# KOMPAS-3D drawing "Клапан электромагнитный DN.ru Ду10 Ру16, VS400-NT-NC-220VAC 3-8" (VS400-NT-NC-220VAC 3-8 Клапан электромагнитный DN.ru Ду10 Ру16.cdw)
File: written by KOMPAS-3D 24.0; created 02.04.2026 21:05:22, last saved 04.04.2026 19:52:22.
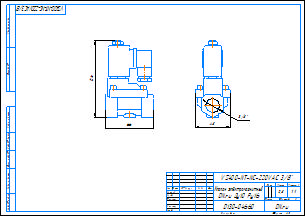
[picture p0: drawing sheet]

Document properties: c3d_UniqueCompID: ef56311e-7521-43dc-8291-0e6108b3d81d; Обозначение: VS400-ET-NC-220VAC 3-8; Наименование: Клапан электромагнитный DN.ru Ду10 Ру16; Автор: artio; Класс точности: c; Знак неуказанной шероховатости: Шероховатость не задана; Рассекать на разрезах: Да; Автор: artio; Форматы листов документа: A3; Полное имя файла: VS400-NT-NC-220VAC 3-8 Клапан электромагнитный DN.ru Ду10 Ру16.m3d; Масса: 0.797; Наименование: Клапан электромагнитный DN.ru Ду10 Ру16; Количество листов документа: 1; Примечание: D130-04660

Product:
- Body: Тело 1  | qty 1
    Масса: 1.030062
- Part/product: Клапан электромагнитный DN.ru Ду10 Ру16  | designation VS400-NT-NC-220VAC 3-8
    Масса: 0.797
    Раздел спецификации: Прочие изделия
    Примечание: D130-04660
    additional columns: ef56311e-7521-43dc-8291-0e6108b3d81d; VS400-ET-NC-220VAC 3-8; artio; c; Шероховатость не задана; Да

Views: Вид 1, Спереди, Проекционный вид 2
Referenced files in C:\Users\artio\OneDrive\Рабочий стол\Клапан электромагнитный DN.ru VS4x-xT-NC-x\DN10\: VS400-ET-NC-220VAC 3-8 Клапан электромагнитный DN.ru Ду10 Ру16.m3d
Referenced files in C:\Users\artio\OneDrive\Рабочий стол\Клапан электромагнитный DN.ru\VS400-NT-NC\VS400-NT-NC-220VAC\: VS400-NT-NC-220VAC 3-8 Клапан электромагнитный DN.ru Ду10 Ру16.m3d, VS400-NT-NC-220VAC 3-8 Клапан электромагнитный DN.ru Ду10 Ру16.cdw
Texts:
  VS400-NT-NC-220VAC 3-8
  Линейный размер
  Клапан электромагнитный
  DN.ru Ду10 Ру16
  VS400-NT-NC-220VAC 3/8"
  VS400-NT-NC-220VAC 3/8"-
  Клапан электромагнитный DN.ru Ду10 Ру16
  VS400-NT-NC-220VAC 3-8 Клапан электромагнитный DN.ru Ду10 Ру16
Dimensions and other numbers on the sheet: 0; 3; 2; 4; 48; 3/8"; 66; 106; 1:1; 1; 0,8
